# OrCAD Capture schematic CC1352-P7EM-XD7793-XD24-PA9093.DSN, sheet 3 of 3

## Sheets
3 Revision
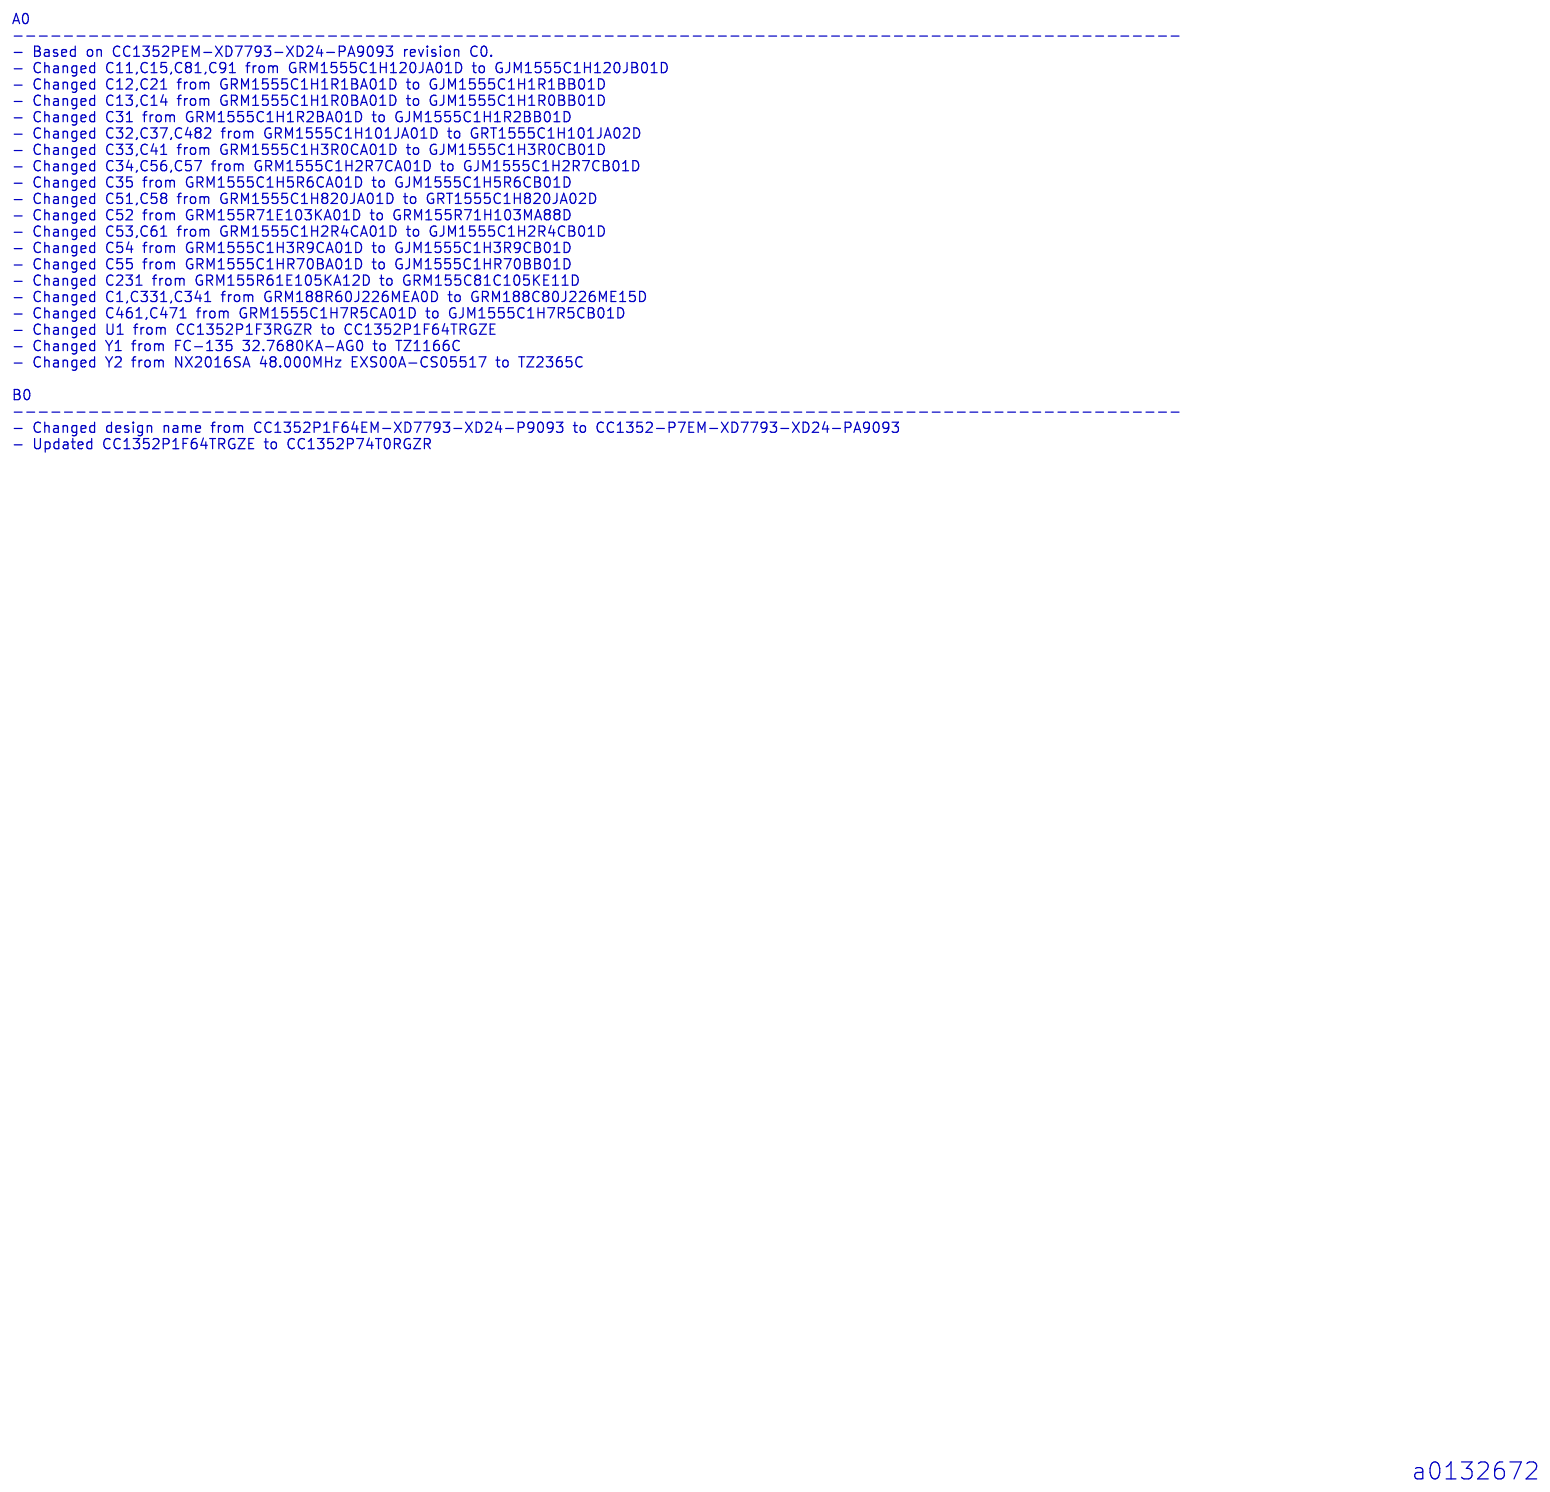
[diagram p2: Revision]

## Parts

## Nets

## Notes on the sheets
sheet 3
- A0
  ---------------------------------------------------------------------------------------------
  - Based on CC1352PEM-XD7793-XD24-PA9093 revision C0.
  - Changed C11,C15,C81,C91 from GRM1555C1H120JA01D to GJM1555C1H120JB01D
  - Changed C12,C21 from GRM1555C1H1R1BA01D to GJM1555C1H1R1BB01D
  - Changed C13,C14 from GRM1555C1H1R0BA01D to GJM1555C1H1R0BB01D
  - Changed C31 from GRM1555C1H1R2BA01D to GJM1555C1H1R2BB01D
  - Changed C32,C37,C482 from GRM1555C1H101JA01D to GRT1555C1H101JA02D
  - Changed C33,C41 from GRM1555C1H3R0CA01D to GJM1555C1H3R0CB01D
  - Changed C34,C56,C57 from GRM1555C1H2R7CA01D to GJM1555C1H2R7CB01D
  - Changed C35 from GRM1555C1H5R6CA01D to GJM1555C1H5R6CB01D
  - Changed C51,C58 from GRM1555C1H820JA01D to GRT1555C1H820JA02D
  - Changed C52 from GRM155R71E103KA01D to GRM155R71H103MA88D
  - Changed C53,C61 from GRM1555C1H2R4CA01D to GJM1555C1H2R4CB01D
  - Changed C54 from GRM1555C1H3R9CA01D to GJM1555C1H3R9CB01D
  - Changed C55 from GRM1555C1HR70BA01D to GJM1555C1HR70BB01D
  - Changed C231 from GRM155R61E105KA12D to GRM155C81C105KE11D
  - Changed C1,C331,C341 from GRM188R60J226MEA0D to GRM188C80J226ME15D
  - Changed C461,C471 from GRM1555C1H7R5CA01D to GJM1555C1H7R5CB01D
  - Changed U1 from CC1352P1F3RGZR to CC1352P1F64TRGZE
  - Changed Y1 from FC-135 32.7680KA-AG0 to TZ1166C
  - Changed Y2 from NX2016SA 48.000MHz EXS00A-CS05517 to TZ2365C
  B0
  ---------------------------------------------------------------------------------------------
  - Changed design name from CC1352P1F64EM-XD7793-XD24-P9093 to CC1352-P7EM-XD7793-XD24-PA9093
  - Updated CC1352P1F64TRGZE to CC1352P74T0RGZR
- a0132672
